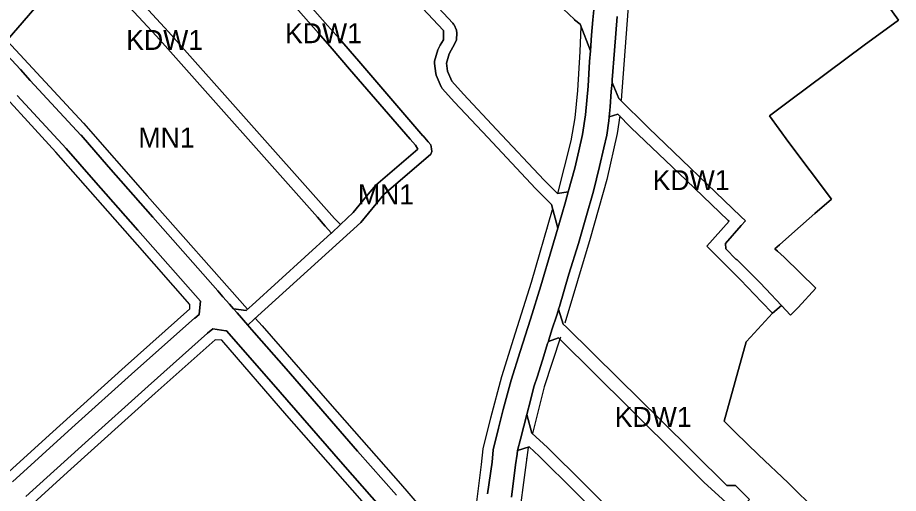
# Model space of a CAD drawing. Extents: x -284239 to -281592, y 34477 to 37267.
# Drawn here: x -283616.2 to -283174, y 35729.6 to 35968.6 of the extents above; entities that cross this region are included whole.
import ezdxf

# ---------------------------------------------------------------- set-up
doc = ezdxf.new("R2010")
doc.units = 0
for name, color, linetype in [('linie_rozgraniczajace', 7, 'Continuous'), ('linie_zabudowy_nieprzekraczalne', 7, 'Continuous'), ('oznaczenia_przeznaczen', 7, 'Continuous')]:
    doc.layers.add(name, color=color, linetype=linetype)

msp = doc.modelspace()

# ---------------------------------------------------------------- linework, layer by layer
at = {"layer": 'linie_rozgraniczajace'}
for points in [[(-283494.569, 36003.366), (-283460.545, 35964.685), (-283454.662, 35957.87), (-283444.953, 35946.621), (-283412.686, 35909.196), (-283412.667, 35909.192), (-283410.091, 35906.206), (-283408.807, 35904.717), (-283408.401, 35902.64), (-283408.273, 35901.359), (-283408.7, 35900.08), (-283432.26, 35879.77), (-283443.87, 35865.76), (-283497.393, 35817.059), (-283500.628, 35814.116), (-283506.027, 35820.265), (-283507.855, 35822.346), (-283501.403, 35821.534), (-283498.504, 35824.126), (-283458.742, 35860.246), (-283458.633, 35860.349), (-283454.071, 35864.661), (-283447.663, 35870.717), (-283440.986, 35878.912), (-283436.34, 35884.457), (-283415.338, 35902.587), (-283416.429, 35904.464), (-283419.115, 35907.463), (-283449.496, 35942.701), (-283458.251, 35952.846), (-283465.066, 35960.742), (-283499.091, 35999.424)], [(-283425.955, 35728.745), (-283445.477, 35750.899), (-283481.409, 35792.231), (-283497.425, 35810.469), (-283499.75, 35813.117), (-283500.628, 35814.116), (-283497.393, 35817.059), (-283443.87, 35865.76), (-283432.26, 35879.77), (-283408.7, 35900.08), (-283408.273, 35901.359), (-283408.401, 35902.64), (-283408.807, 35904.717), (-283410.091, 35906.206), (-283412.667, 35909.192), (-283412.686, 35909.196), (-283444.953, 35946.621), (-283454.662, 35957.87), (-283460.545, 35964.685), (-283494.569, 36003.366)], [(-283576.638, 36000.7), (-283540.379, 35961.4), (-283461.111, 35872.15), (-283457.125, 35867.663), (-283457.037, 35867.736), (-283454.071, 35864.661), (-283458.633, 35860.349), (-283461.717, 35863.797), (-283465.703, 35868.285), (-283544.824, 35957.369), (-283548.7, 35961.565), (-283548.885, 35961.766), (-283580.055, 35995.51)], [(-283499.091, 35999.424), (-283465.066, 35960.742), (-283458.251, 35952.846), (-283449.496, 35942.701), (-283419.115, 35907.463), (-283416.429, 35904.464), (-283415.338, 35902.587), (-283436.34, 35884.457), (-283440.986, 35878.912), (-283447.663, 35870.717), (-283454.071, 35864.661), (-283457.037, 35867.736), (-283457.125, 35867.663), (-283461.111, 35872.15), (-283540.379, 35961.4), (-283576.638, 36000.7)], [(-283580.055, 35995.51), (-283548.885, 35961.766), (-283548.7, 35961.565), (-283544.824, 35957.369), (-283465.703, 35868.285), (-283461.717, 35863.797), (-283458.633, 35860.349), (-283458.742, 35860.246), (-283498.504, 35824.126), (-283501.403, 35821.534), (-283507.855, 35822.346), (-283509.885, 35824.657), (-283513.115, 35828.336), (-283515.705, 35831.284), (-283548.315, 35868.418), (-283570.539, 35893.688), (-283584.386, 35909.474), (-283584.432, 35909.507), (-283584.473, 35909.57), (-283609.881, 35937.063), (-283614.852, 35942.44), (-283621.467, 35949.769)], [(-283367.894, 35997.315), (-283336.674, 35967.549), (-283336.625, 35967.518), (-283336.598, 35967.48), (-283333.711, 35965.253), (-283328.608, 35951.956), (-283329.016, 35946.503), (-283329.797, 35934.154), (-283331.1, 35919.823), (-283332.559, 35909.819), (-283334.383, 35901.742), (-283336.363, 35892.883), (-283339.733, 35881), (-283345.21, 35880.166), (-283351.894, 35886.876), (-283375.74, 35912.438), (-283392.392, 35930.148), (-283398.258, 35936.638), (-283400.4, 35941.6), (-283400.876, 35945.67), (-283399.547, 35950.431), (-283398.527, 35952.217), (-283397.615, 35953.812), (-283396.126, 35956.534), (-283395.906, 35957.452), (-283395.641, 35960.891), (-283395.658, 35960.995), (-283395.633, 35961.121), (-283395.809, 35961.943), (-283395.861, 35962.269), (-283395.888, 35962.309), (-283395.897, 35962.352), (-283397.088, 35964.998), (-283397.342, 35965.367), (-283397.628, 35965.812), (-283419.135, 35988.903)], [(-283326.952, 35972.467), (-283327.42, 35967.384), (-283328.022, 35959.803), (-283328.608, 35951.956), (-283333.711, 35965.253), (-283336.598, 35967.48), (-283336.625, 35967.518), (-283336.674, 35967.549), (-283367.894, 35997.315)], [(-283419.135, 35988.903), (-283397.628, 35965.812), (-283397.342, 35965.367), (-283397.088, 35964.998), (-283395.897, 35962.352), (-283395.888, 35962.309), (-283395.861, 35962.269), (-283395.809, 35961.943), (-283395.633, 35961.121), (-283395.658, 35960.995), (-283395.641, 35960.891), (-283395.906, 35957.452), (-283396.126, 35956.534), (-283397.615, 35953.812), (-283398.527, 35952.217), (-283399.547, 35950.431), (-283400.876, 35945.67), (-283400.4, 35941.6), (-283398.258, 35936.638), (-283392.392, 35930.148), (-283375.74, 35912.438), (-283351.894, 35886.876), (-283345.21, 35880.166), (-283339.733, 35881), (-283341.131, 35876.072), (-283342.935, 35869.765), (-283344.983, 35862.75), (-283348.081, 35874.783), (-283356.244, 35882.742), (-283380.119, 35908.337), (-283396.783, 35926.06), (-283396.812, 35926.095), (-283403.041, 35932.982), (-283403.444, 35933.62), (-283403.57, 35933.805), (-283406.086, 35939.636), (-283406.101, 35939.667), (-283406.309, 35940.466), (-283406.904, 35945.56), (-283406.924, 35945.908), (-283406.814, 35946.714), (-283405.226, 35952.403), (-283405.109, 35952.745), (-283404.942, 35953.085), (-283404.002, 35954.729), (-283402.341, 35957.422), (-283402.356, 35962.085), (-283423.5, 35984.79)], [(-283187.253, 35986.027), (-283173.975, 35967.24), (-283191.172, 35954.733), (-283228.673, 35926.813), (-283228.674, 35926.736), (-283238.654, 35919.327), (-283228.924, 35905.891), (-283207.632, 35877.424), (-283215.881, 35870.146), (-283225.929, 35861.349), (-283233.742, 35854.508), (-283236.024, 35852.506), (-283234.725, 35851.304), (-283231.39, 35848.22), (-283215.4, 35832.65), (-283224.37, 35823.07), (-283228.09, 35819.1), (-283232.707, 35824.029), (-283240.586, 35832.442), (-283243.46, 35835.51), (-283255.153, 35847.019), (-283255.347, 35847.148), (-283260.65, 35852.43), (-283260.71, 35855.21), (-283252.91, 35864.097), (-283250.79, 35866.51), (-283253.132, 35868.761), (-283299.41, 35913.25), (-283314.311, 35927.906), (-283317.76, 35936.031), (-283317.656, 35937.332), (-283316.458, 35952.079), (-283315.155, 35969.119)], [(-283261.405, 35765.965), (-283250.36, 35805.79), (-283248.257, 35808.092), (-283237.133, 35820.109), (-283232.707, 35824.029), (-283228.09, 35819.1), (-283224.37, 35823.07), (-283215.4, 35832.65), (-283231.39, 35848.22), (-283234.725, 35851.304), (-283236.024, 35852.506), (-283233.742, 35854.508), (-283225.929, 35861.349), (-283215.881, 35870.146), (-283207.632, 35877.424), (-283228.924, 35905.891), (-283238.654, 35919.327), (-283228.674, 35926.736), (-283228.673, 35926.813), (-283191.172, 35954.733), (-283173.975, 35967.24), (-283187.253, 35986.027)], [(-283423.5, 35984.79), (-283402.356, 35962.085), (-283402.341, 35957.422), (-283404.002, 35954.729), (-283404.942, 35953.085), (-283405.109, 35952.745), (-283405.226, 35952.403), (-283406.814, 35946.714), (-283406.924, 35945.908), (-283406.904, 35945.56), (-283406.309, 35940.466), (-283406.101, 35939.667), (-283406.086, 35939.636), (-283403.57, 35933.805), (-283403.444, 35933.62), (-283403.041, 35932.982), (-283396.812, 35926.095), (-283396.783, 35926.06), (-283380.119, 35908.337), (-283356.244, 35882.742), (-283348.081, 35874.783), (-283344.983, 35862.75), (-283347.931, 35852.655), (-283353.507, 35833.948), (-283358.77, 35817.117), (-283363.825, 35800.807), (-283368.462, 35786.477), (-283372.371, 35771.73), (-283374.716, 35762.402), (-283377.425, 35751.563), (-283377.998, 35745.258), (-283380.239, 35729.365)], [(-283621.534, 35957.2), (-283602.166, 35979.602)], [(-283602.166, 35979.602), (-283621.534, 35957.2)], [(-283380.239, 35729.365), (-283377.998, 35745.258), (-283377.425, 35751.563), (-283374.716, 35762.402), (-283372.371, 35771.73), (-283368.462, 35786.477), (-283363.825, 35800.807), (-283358.77, 35817.117), (-283353.507, 35833.948), (-283347.931, 35852.655), (-283344.983, 35862.75), (-283342.935, 35869.765), (-283341.131, 35876.072), (-283339.733, 35881), (-283336.363, 35892.883), (-283334.383, 35901.742), (-283332.559, 35909.819), (-283331.1, 35919.823), (-283329.797, 35934.154), (-283329.016, 35946.503), (-283328.608, 35951.956), (-283328.022, 35959.803), (-283327.42, 35967.384), (-283326.952, 35972.467)], [(-283315.155, 35969.119), (-283316.458, 35952.079), (-283317.656, 35937.332), (-283317.76, 35936.031), (-283318.129, 35931.453), (-283318.74, 35923.807), (-283319.198, 35918.719), (-283319.376, 35916.749), (-283320.418, 35909.558), (-283321.825, 35903.149), (-283324.013, 35893.873), (-283325.472, 35887.62), (-283327.14, 35881.367), (-283330.944, 35867.975), (-283334.644, 35855.208), (-283339.385, 35839.732), (-283344.157, 35823.526), (-283344.561, 35822.155), (-283344.649, 35821.859), (-283345.668, 35818.639), (-283347.736, 35812.259), (-283349.502, 35806.716), (-283349.735, 35805.983), (-283350.089, 35804.874), (-283352.048, 35798.722), (-283355.175, 35788.509), (-283356.998, 35783.142), (-283358.666, 35776.263), (-283360.471, 35769.281), (-283361.964, 35763.457), (-283363.633, 35756.862)], [(-283621.467, 35949.769), (-283614.852, 35942.44), (-283609.881, 35937.063), (-283584.473, 35909.57), (-283584.432, 35909.507), (-283584.386, 35909.474), (-283570.539, 35893.688), (-283548.315, 35868.418), (-283515.705, 35831.284), (-283513.115, 35828.336), (-283509.885, 35824.657), (-283507.855, 35822.346), (-283506.027, 35820.265), (-283500.628, 35814.116), (-283499.75, 35813.117), (-283497.425, 35810.469), (-283481.409, 35792.231), (-283445.477, 35750.899), (-283425.955, 35728.745)], [(-283618.835, 35735.513), (-283588.953, 35762.48), (-283557.318, 35791.004), (-283527.417, 35817.597), (-283527.305, 35817.696), (-283525.143, 35819.497), (-283525.143, 35819.586), (-283524.471, 35826.219), (-283555.821, 35861.811), (-283578.052, 35887.089), (-283591.861, 35902.831), (-283616.44, 35929.426)], [(-283616.44, 35929.426), (-283591.861, 35902.831), (-283578.052, 35887.089), (-283555.821, 35861.811), (-283524.471, 35826.219), (-283525.143, 35819.586), (-283525.143, 35819.497), (-283527.305, 35817.696), (-283527.417, 35817.597), (-283557.318, 35791.004), (-283588.953, 35762.48), (-283618.835, 35735.513)], [(-283248.69, 35726.59), (-283255.81, 35733.62), (-283258.538, 35733.588), (-283260.03, 35733.57), (-283293.67, 35766.75), (-283314.405, 35787.199), (-283340.653, 35813.099), (-283342.259, 35814.684), (-283344.561, 35822.155), (-283344.157, 35823.526), (-283339.385, 35839.732), (-283334.644, 35855.208), (-283330.944, 35867.975), (-283327.14, 35881.367), (-283325.472, 35887.62), (-283324.013, 35893.873), (-283321.825, 35903.149), (-283320.418, 35909.558), (-283319.376, 35916.749), (-283319.198, 35918.719), (-283314.781, 35920.138), (-283308.088, 35913.292), (-283280.46, 35886.96), (-283259.436, 35866.728), (-283258.97, 35866.28), (-283270.16, 35853.82), (-283268.076, 35851.736), (-283253.18, 35836.84), (-283242.669, 35825.832), (-283237.133, 35820.109), (-283248.257, 35808.092), (-283250.36, 35805.79), (-283261.405, 35765.965), (-283255.713, 35760.273), (-283244.23, 35749.073), (-283229.344, 35734.896), (-283214.743, 35720.578)], [(-283433.469, 35722.148), (-283452.999, 35744.31), (-283488.946, 35785.659), (-283511.373, 35811.298), (-283511.674, 35811.312), (-283518.216, 35812.259), (-283520.842, 35810.065), (-283550.644, 35783.558), (-283582.255, 35755.055), (-283612.122, 35728.101)], [(-283612.122, 35728.101), (-283582.255, 35755.055), (-283550.644, 35783.558), (-283520.842, 35810.065), (-283518.216, 35812.259), (-283511.674, 35811.312), (-283511.373, 35811.298), (-283488.946, 35785.659), (-283452.999, 35744.31), (-283433.469, 35722.148)], [(-283360.471, 35769.281), (-283358.666, 35776.263), (-283356.998, 35783.142), (-283355.175, 35788.509), (-283352.048, 35798.722), (-283350.089, 35804.874), (-283349.735, 35805.983), (-283344.662, 35807.672), (-283343.987, 35807.004), (-283309.22, 35772.58), (-283304.28, 35767.69), (-283286.84, 35750.42), (-283271.48, 35735.12), (-283255.01, 35720.19)], [(-283317.814, 35712.15), (-283354.266, 35748.338), (-283359.347, 35752.962), (-283365.201, 35751.171), (-283363.633, 35756.862), (-283361.964, 35763.457), (-283360.471, 35769.281), (-283357.966, 35759.818), (-283350.179, 35752.731), (-283350.143, 35752.681), (-283350.085, 35752.642), (-283313.572, 35716.394)], [(-283313.572, 35716.394), (-283350.085, 35752.642), (-283350.143, 35752.681), (-283350.179, 35752.731), (-283357.966, 35759.818), (-283360.471, 35769.281)], [(-283229.344, 35734.896), (-283244.23, 35749.073), (-283255.713, 35760.273), (-283261.405, 35765.965)], [(-283363.633, 35756.862), (-283365.201, 35751.171), (-283365.44, 35749.375), (-283366.17, 35743.956), (-283368.254, 35727.698)], [(-283368.254, 35727.698), (-283366.17, 35743.956), (-283365.44, 35749.375), (-283365.201, 35751.171), (-283359.347, 35752.962), (-283354.266, 35748.338), (-283317.814, 35712.15)], [(-283214.743, 35720.578), (-283229.344, 35734.896)]]:
    msp.add_lwpolyline(points, dxfattribs=at)
for points in [[(-283319.198, 35918.719), (-283318.74, 35923.807), (-283318.129, 35931.453), (-283317.76, 35936.031), (-283314.311, 35927.906), (-283299.41, 35913.25), (-283253.132, 35868.761), (-283250.79, 35866.51), (-283252.91, 35864.097), (-283260.71, 35855.21), (-283260.65, 35852.43), (-283255.347, 35847.148), (-283255.153, 35847.019), (-283243.46, 35835.51), (-283240.586, 35832.442), (-283232.707, 35824.029), (-283237.133, 35820.109), (-283242.669, 35825.832), (-283253.18, 35836.84), (-283268.076, 35851.736), (-283270.16, 35853.82), (-283258.97, 35866.28), (-283259.436, 35866.728), (-283280.46, 35886.96), (-283308.088, 35913.292), (-283314.781, 35920.138)], [(-283349.735, 35805.983), (-283349.502, 35806.716), (-283347.736, 35812.259), (-283345.668, 35818.639), (-283344.649, 35821.859), (-283344.561, 35822.155), (-283342.259, 35814.684), (-283340.653, 35813.099), (-283314.405, 35787.199), (-283293.67, 35766.75), (-283260.03, 35733.57), (-283258.538, 35733.588), (-283255.81, 35733.62), (-283248.69, 35726.59), (-283255.01, 35720.19), (-283271.48, 35735.12), (-283286.84, 35750.42), (-283304.28, 35767.69), (-283309.22, 35772.58), (-283343.987, 35807.004), (-283344.662, 35807.672)]]:
    msp.add_lwpolyline(points, close=True, dxfattribs=at)
at = {"layer": 'linie_zabudowy_nieprzekraczalne'}
for points in [[(-283184.989, 36052.24), (-283189.884, 36081.873), (-283196.763, 36116.534), (-283209.86, 36100.659), (-283221.369, 36089.546), (-283226.661, 36084.784), (-283242.007, 36072.745), (-283251.003, 36065.998), (-283261.454, 36058.259), (-283272.037, 36051.116), (-283276.535, 36047.015), (-283288.441, 36033.388), (-283299.686, 36021.614), (-283305.375, 36014.405), (-283308.02, 36003.424), (-283308.153, 35994.164), (-283310.402, 35965.126), (-283313.189, 35927.062)], [(-283344.939, 35880.231), (-283338.315, 35906.653), (-283336.331, 35918.162), (-283334.876, 35932.053), (-283333.685, 35951.5), (-283333.298, 35964.104)], [(-283621.43, 35956.96), (-283583.055, 35915.583), (-283551.173, 35879.136), (-283500.779, 35822.096)], [(-283529.742, 35822.383), (-283529.742, 35824.5), (-283556.068, 35854.464), (-283597.078, 35900.964), (-283634.13, 35941.482)], [(-283313.851, 35919.257), (-283315.164, 35910.357), (-283320.324, 35887.272), (-283328.658, 35857.572), (-283341.5, 35815.143)], [(-283496.86, 35817.549), (-283493.494, 35813.784), (-283459.495, 35774.758), (-283423.908, 35734.343), (-283389.645, 35694.655), (-283386.205, 35721.312), (-283383.295, 35744.066), (-283382.501, 35752.004), (-283378.664, 35767.548), (-283373.108, 35788.318), (-283366.229, 35810.212), (-283358.159, 35835.744), (-283347.585, 35872.161)], [(-283350.222, 35862.666), (-283350.257, 35862.804)], [(-283703.254, 35666.597), (-283669.574, 35696.441), (-283633.723, 35728.654), (-283600.253, 35759.015), (-283562.286, 35793.411), (-283529.742, 35822.383)], [(-283439.519, 35721.51), (-283481.058, 35768.805), (-283513.734, 35806.508), (-283517.042, 35806.772), (-283547.204, 35779.983), (-283591.125, 35740.362), (-283640.338, 35695.581)], [(-283343.617, 35808.131), (-283351.809, 35783.224), (-283357.64, 35759.713)], [(-283359.888, 35752.701), (-283366.097, 35706.098), (-283369.801, 35676.597), (-283364.377, 35665.22), (-283341.358, 35650.999), (-283311.857, 35634.991), (-283300.612, 35629.633), (-283277.726, 35620.241), (-283261.189, 35613.097), (-283252.193, 35607.938), (-283239.758, 35600.265), (-283222.692, 35586.374), (-283216.21, 35581.876), (-283209.331, 35578.172), (-283204.304, 35577.51), (-283200.599, 35577.643), (-283185.395, 35579.399)], [(-283360.407, 35747.114), (-283360.673, 35747.373)]]:
    msp.add_lwpolyline(points, dxfattribs=at)

# ---------------------------------------------------------------- texts
at = {"layer": 'oznaczenia_przeznaczen'}
for s, p in [('KDW1', (-283481.951, 35955.742)), ('KDW1', (-283561.709, 35952.369)), ('MN1', (-283555.554, 35903.343)), ('KDW1', (-283297.345, 35881.96)), ('MN1', (-283445.389, 35874.77)), ('KDW1', (-283316.404, 35763.04))]:
    msp.add_text(s, height=10, dxfattribs=at).set_placement(p)

doc.saveas('drawing.dxf')
